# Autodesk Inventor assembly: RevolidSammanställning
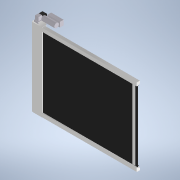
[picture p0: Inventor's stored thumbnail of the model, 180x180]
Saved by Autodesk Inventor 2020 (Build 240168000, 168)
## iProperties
Created: 2019-06
Part Number: RevolidSammanställning
Document SubType Name: Assembly
Designer: cl
Author: cl
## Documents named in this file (13)
- G:\AutoCad\Carl Lund\Revolid\RevolidSammanställning.iam
- G:\AutoCad\Carl Lund\Revolid\RevolidStyrande.iam
- G:\AutoCad\Carl Lund\Revolid\Parts\Duk.ipt
- G:\AutoCad\Carl Lund\Revolid\Parts\SidoProfil.ipt
- G:\AutoCad\Carl Lund\Revolid\Parts\Trummkåpa.ipt
- G:\AutoCad\Carl Lund\Revolid\Parts\NedreBalk.ipt
- G:\AutoCad\Carl Lund\Revolid\Parts\Tätningslist.ipt
- G:\AutoCad\Carl Lund\Revolid\Parts\Motorfäste.ipt
- G:\AutoCad\Carl Lund\Revolid\Parts\Växellåda.ipt
- G:\AutoCad\Carl Lund\Revolid\Parts\Motor.ipt
- G:\AutoCad\Carl Lund\Revolid\Parts\Avbländare.ipt
- G:\AutoCad\Carl Lund\Revolid\Parts\Avbländarbit.ipt
- G:\AutoCad\Carl Lund\Revolid\Parts\VäxellådaGrå.ipt
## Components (14 placed, 11 different names)
1. Duk:1 — Mate:1, Flush:2, Mate:2, Flush:3, Flush:7, Flush:8, Flush:9, Flush:17, Mate:12, Mate:15
2. SidoProfil:1 — Mate:2, Flush:3, Mate:3, Flush:5, Flush:6, Flush:9
3. SidoProfil:2 — Mate:1, Flush:2, Mate:5, Flush:8
4. Trummkåpa:1 — Mate:3, Flush:5, Flush:6, Mate:7, Flush:12, Flush:13
5. NedreBalk:1 — Mate:5, Flush:7, Mate:6, Flush:10, Flush:11, Mate:10, Flush:18, Mate:13, Flush:21, Mate:18, Mate:19
6. Tätningslist:1 — Mate:6, Flush:10, Flush:11, Flush:17
7. Motorfäste:1 — Mate:7, Flush:12, Flush:13, Mate:8, Mate:16, Flush:24, Flush:25
8. Växellåda:1 — Mate:8, Mate:9, Flush:16, Tangent:1, Flush:26, Mate:17
9. Motor:1 — Mate:9, Flush:16, Tangent:1
10. Avbländare:1 — Mate:10, Flush:18, Mate:11, Flush:20, Mate:19
11. Avbländarbit:1 — Mate:11, Flush:20, Mate:12
12. Avbländare:2 — Mate:13, Flush:21, Mate:14, Flush:23, Mate:18
13. Avbländarbit:2 — Mate:14, Flush:23, Mate:15
14. VäxellådaGrå:1 — Mate:16, Flush:24, Flush:25, Flush:26, Mate:17
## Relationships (39: Flush 20, Mate 18, Tangent 1)
- Mate:1: Duk:1 ↔ SidoProfil:2
- Flush:2: Duk:1 ↔ SidoProfil:2
- Mate:2: Duk:1 ↔ SidoProfil:1
- Flush:3: Duk:1 ↔ SidoProfil:1
- Mate:3: SidoProfil:1 ↔ Trummkåpa:1
- Flush:5: SidoProfil:1 ↔ Trummkåpa:1
- Flush:6: SidoProfil:1 ↔ Trummkåpa:1
- Mate:5: SidoProfil:2 ↔ NedreBalk:1
- Flush:7: Duk:1 ↔ NedreBalk:1
- Flush:8: Duk:1 ↔ SidoProfil:2
- Flush:9: Duk:1 ↔ SidoProfil:1
- Mate:6: NedreBalk:1 ↔ Tätningslist:1
- Flush:10: NedreBalk:1 ↔ Tätningslist:1
- Flush:11: NedreBalk:1 ↔ Tätningslist:1
- Mate:7: Trummkåpa:1 ↔ Motorfäste:1
- Flush:12: Trummkåpa:1 ↔ Motorfäste:1
- Flush:13: Trummkåpa:1 ↔ Motorfäste:1
- Mate:8: Motorfäste:1 ↔ Växellåda:1
- Mate:9: Växellåda:1 ↔ Motor:1
- Flush:16: Växellåda:1 ↔ Motor:1
- Tangent:1: Växellåda:1 ↔ Motor:1
- Flush:17: Duk:1 ↔ Tätningslist:1
- Mate:10: NedreBalk:1 ↔ Avbländare:1
- Flush:18: NedreBalk:1 ↔ Avbländare:1
- Mate:11: Avbländare:1 ↔ Avbländarbit:1
- Flush:20: Avbländare:1 ↔ Avbländarbit:1
- Mate:12: Duk:1 ↔ Avbländarbit:1
- Mate:13: NedreBalk:1 ↔ Avbländare:2
- Flush:21: NedreBalk:1 ↔ Avbländare:2
- Mate:14: Avbländare:2 ↔ Avbländarbit:2
- Flush:23: Avbländare:2 ↔ Avbländarbit:2
- Mate:15: Duk:1 ↔ Avbländarbit:2
- Mate:16: Motorfäste:1 ↔ VäxellådaGrå:1
- Flush:24: Motorfäste:1 ↔ VäxellådaGrå:1
- Flush:25: Motorfäste:1 ↔ VäxellådaGrå:1
- Flush:26: Växellåda:1 ↔ VäxellådaGrå:1
- Mate:17: Växellåda:1 ↔ VäxellådaGrå:1
- Mate:18: NedreBalk:1 ↔ Avbländare:2
- Mate:19: NedreBalk:1 ↔ Avbländare:1
